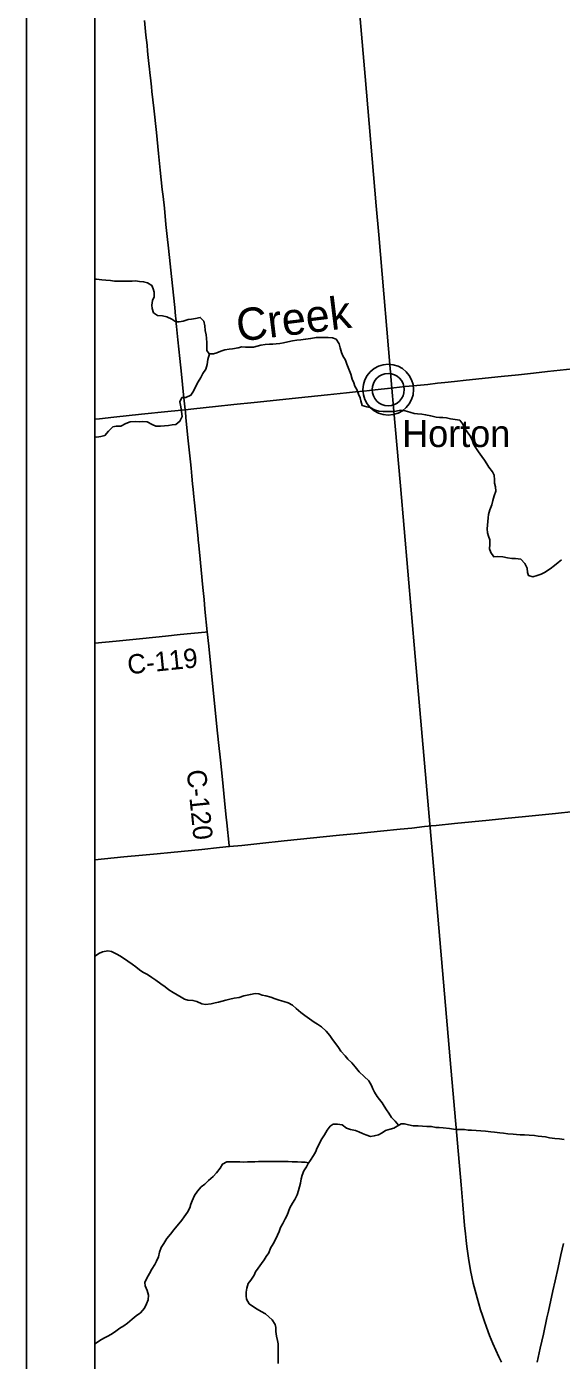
# Model space of a CAD drawing. Extents: x 0 to 34, y 0 to 22.
# Drawn here: x 2 to 2.784, y 18.655 to 20.61 of the extents above; entities that cross this region are included whole.
import ezdxf

# ---------------------------------------------------------------- set-up
doc = ezdxf.new("R2010")
doc.units = 0
for name, color, linetype in [('GM_X_Corporation', 7, 'Continuous'), ('GM_X_County_Road', 7, 'Continuous'), ('GM_X_County_Road_Text', 7, 'Continuous'), ('GM_X_Minor_River', 7, 'Continuous'), ('GM_X_Minor_River_Text', 7, 'Continuous'), ('GM_X_Rail_Line', 7, 'Continuous'), ('GM_X_Unincorporated', 7, 'Continuous'), ('GM_X_Unincorporated_Location', 7, 'Continuous'), ('GM_X_Unincorporated_Text', 7, 'Continuous'), ('SH_Data', 7, 'Continuous')]:
    doc.layers.add(name, color=color, linetype=linetype)

msp = doc.modelspace()

# ---------------------------------------------------------------- linework, layer by layer
at = {"layer": 'GM_X_Corporation'}
msp.add_lwpolyline([(2.8444, 15.5792), (2.8939, 16.1007), (2.9069, 16.2381), (2.9254, 16.4061), (2.988, 17.0603), (3.0331, 17.5172), (3.0637, 17.8164), (3.0931, 18.1263), (3.1112, 18.3014), (3.1559, 18.7686), (3.1859, 19.0395), (3.2287, 19.5029), (3.2417, 19.6403), (3.2592, 19.8236), (3.2953, 20.1573), (3.3575, 20.7908), (3.3687, 20.9), (2.1, 20.9), (2.1, 14.1)], dxfattribs=at)
msp.add_lwpolyline([(3.3687, 20.9), (2.1, 20.9), (2.1, 18.2085), (2.1311, 18.2055), (2.4093, 18.1831), (2.8083, 18.1509), (3.0252, 18.1335), (3.0931, 18.1263), (3.1112, 18.3014), (3.1559, 18.7686), (3.1859, 19.0395), (3.2287, 19.5029), (3.2417, 19.6403), (3.2592, 19.8236), (3.2953, 20.1573), (3.3575, 20.7908)], close=True, dxfattribs=at)
at = {"layer": 'GM_X_County_Road'}
for points in [[(2.2649, 19.7224), (2.2615, 19.7559), (2.2601, 19.7698), (2.2584, 19.7875), (2.2533, 19.8391), (2.2519, 19.8533), (2.2515, 19.8571), (2.2513, 19.8592), (2.246, 19.9118), (2.2447, 19.9255), (2.2441, 19.9316), (2.2433, 19.9388), (2.2427, 19.9452), (2.2422, 19.9507), (2.2416, 19.9566), (2.241, 19.9625), (2.2402, 19.9715), (2.2365, 20.0067), (2.235, 20.0222), (2.2336, 20.0364), (2.2327, 20.0456), (2.2324, 20.048), (2.2319, 20.0524), (2.2302, 20.0698), (2.2271, 20.1004), (2.2247, 20.1232), (2.2219, 20.1507), (2.2199, 20.1699), (2.2194, 20.1747), (2.2191, 20.1781), (2.2187, 20.1823), (2.2183, 20.1854), (2.2171, 20.198), (2.2137, 20.2299), (2.2078, 20.2849), (2.2061, 20.3021), (2.2043, 20.3195), (2.2019, 20.3433), (2.2, 20.3606), (2.1989, 20.3708), (2.1959, 20.3992), (2.1933, 20.4236), (2.1902, 20.4545), (2.1864, 20.4903), (2.1837, 20.5147), (2.183, 20.5212), (2.182, 20.5302), (2.1807, 20.5422), (2.1802, 20.5472), (2.1793, 20.5555), (2.1784, 20.5644), (2.1774, 20.5737), (2.1765, 20.5823), (2.1749, 20.5969), (2.1726, 20.6185)], [(2.1, 20.0341), (2.107, 20.0349), (2.128, 20.0372), (2.1682, 20.0414), (2.2071, 20.0453), (2.2222, 20.047), (2.2324, 20.048), (2.2451, 20.0493), (2.2769, 20.0527), (2.3038, 20.0557), (2.3338, 20.0589), (2.3662, 20.0622), (2.3987, 20.0656), (2.4413, 20.07), (2.4691, 20.073), (2.4821, 20.0742), (2.4945, 20.0755), (2.5112, 20.0773), (2.5337, 20.0797), (2.5386, 20.0802), (2.555, 20.082), (2.5668, 20.0831), (2.5881, 20.0853), (2.6023, 20.0869), (2.6131, 20.0881), (2.6273, 20.0897), (2.6446, 20.0915), (2.6956, 20.0968), (2.7213, 20.0993), (2.7432, 20.1017), (2.7639, 20.1039), (2.801, 20.1078)], [(2.1, 19.7059), (2.1312, 19.7089), (2.1705, 19.713), (2.2035, 19.7163), (2.2252, 19.7184), (2.2616, 19.7221), (2.2649, 19.7224)], [(2.2973, 19.4077), (2.2971, 19.4094), (2.2935, 19.4428), (2.2926, 19.4508), (2.291, 19.465), (2.287, 19.5059), (2.2842, 19.5343), (2.2815, 19.5603), (2.279, 19.5834), (2.2749, 19.623), (2.2725, 19.6468), (2.2704, 19.6669), (2.267, 19.7015), (2.2649, 19.7224)], [(2.1, 19.3883), (2.1426, 19.3926), (2.1701, 19.3952), (2.1914, 19.3972), (2.2115, 19.3993), (2.2567, 19.4037), (2.2826, 19.4063), (2.2969, 19.4077), (2.2973, 19.4077), (2.3157, 19.4096), (2.3417, 19.4123), (2.3778, 19.416), (2.4588, 19.4243), (2.4857, 19.4271), (2.5188, 19.4304), (2.5479, 19.4333), (2.5649, 19.435), (2.5834, 19.437), (2.589, 19.4377), (2.593, 19.438), (2.6007, 19.4389), (2.6276, 19.4416), (2.678, 19.4466), (2.7012, 19.4489), (2.7315, 19.4519), (2.7757, 19.4564), (2.8023, 19.4592)], [(2.7488, 18.6522), (2.7532, 18.6726), (2.7577, 18.6932), (2.763, 18.717), (2.7652, 18.7268), (2.7716, 18.7564), (2.7748, 18.7712), (2.7792, 18.7909), (2.7833, 18.8094), (2.7871, 18.8261)]]:
    msp.add_lwpolyline(points, dxfattribs=at)
at = {"layer": 'GM_X_Minor_River'}
for points in [[(2.4635, 20.1273), (2.4615, 20.1321), (2.4599, 20.1386), (2.4584, 20.1449), (2.4538, 20.1516), (2.4487, 20.1535), (2.4423, 20.1538), (2.4372, 20.1539), (2.4304, 20.154), (2.4247, 20.1539), (2.4165, 20.1527), (2.4091, 20.1513), (2.4023, 20.1506), (2.3964, 20.1501), (2.39, 20.1491), (2.3828, 20.1476), (2.3765, 20.1462), (2.3712, 20.1453), (2.3661, 20.1445), (2.3611, 20.1442), (2.356, 20.144), (2.35, 20.1436), (2.3435, 20.1425), (2.3382, 20.1411), (2.3325, 20.14), (2.3278, 20.1397), (2.3209, 20.14), (2.3156, 20.1401), (2.3103, 20.139), (2.3018, 20.1372), (2.297, 20.1369), (2.2908, 20.136), (2.2849, 20.1337), (2.2788, 20.1317), (2.2739, 20.13), (2.2676, 20.1299), (2.2641, 20.1347), (2.2641, 20.1395), (2.2642, 20.1461), (2.2636, 20.1528), (2.2631, 20.1577), (2.262, 20.1642), (2.2615, 20.171), (2.2599, 20.1777), (2.2545, 20.1833), (2.2477, 20.182), (2.2416, 20.1806), (2.2369, 20.1801), (2.2296, 20.1781), (2.2236, 20.1771), (2.2186, 20.1769), (2.213, 20.1806), (2.2055, 20.1843), (2.1991, 20.1856), (2.1919, 20.1864), (2.1861, 20.1903), (2.1841, 20.1964), (2.1836, 20.2012), (2.1846, 20.208), (2.187, 20.2138), (2.1869, 20.2205), (2.1854, 20.2254), (2.1838, 20.2302), (2.177, 20.2339), (2.1714, 20.2357), (2.1653, 20.2362), (2.1596, 20.237), (2.1545, 20.2367), (2.149, 20.2366), (2.1441, 20.2367), (2.1367, 20.2366), (2.1288, 20.2367), (2.1229, 20.2373), (2.1159, 20.238), (2.1104, 20.2387), (2.1025, 20.2393), (2.1, 20.2394)], [(2.2679, 20.1299), (2.2658, 20.1218), (2.2647, 20.1144), (2.2628, 20.1076), (2.2585, 20.1014), (2.2556, 20.0955), (2.2517, 20.089), (2.2482, 20.0827), (2.2445, 20.0752), (2.2409, 20.0692), (2.2334, 20.0662), (2.2276, 20.0658), (2.2248, 20.0595), (2.2262, 20.0523), (2.2273, 20.0456), (2.2278, 20.0384), (2.2248, 20.0311), (2.2189, 20.0264), (2.2136, 20.0259), (2.2081, 20.0252), (2.202, 20.0247), (2.1965, 20.0241), (2.1893, 20.024), (2.184, 20.0265), (2.1767, 20.0304), (2.1703, 20.0309), (2.1652, 20.0304), (2.1589, 20.0309), (2.1519, 20.0302), (2.1454, 20.0278), (2.1382, 20.0241), (2.1314, 20.0238), (2.1266, 20.0228), (2.1201, 20.0166), (2.1147, 20.0104), (2.1086, 20.0088), (2.103, 20.0081), (2.1, 20.0086)], [(2.7843, 19.8279), (2.7795, 19.8242), (2.7742, 19.8197), (2.7677, 19.8147), (2.7593, 19.8095), (2.7543, 19.8071), (2.7486, 19.8051), (2.7423, 19.8032), (2.7361, 19.8049), (2.7343, 19.8096), (2.7338, 19.8161), (2.7303, 19.8228), (2.7245, 19.8291), (2.7169, 19.8302), (2.7115, 19.8301), (2.7052, 19.8309), (2.6981, 19.8327), (2.691, 19.8328), (2.685, 19.8325), (2.6809, 19.8389), (2.6789, 19.844), (2.679, 19.8507), (2.6793, 19.8573), (2.6774, 19.8627), (2.6758, 19.8678), (2.6753, 19.8737), (2.6756, 19.879), (2.6764, 19.8845), (2.6767, 19.8898), (2.6773, 19.8946), (2.6793, 19.9016), (2.682, 19.9085), (2.6834, 19.915), (2.6854, 19.922), (2.6878, 19.9286), (2.6873, 19.9349), (2.6862, 19.9404), (2.6863, 19.9453), (2.6858, 19.952), (2.6829, 19.9571), (2.6779, 19.9637), (2.6747, 19.969), (2.6714, 19.9744), (2.6673, 19.9796), (2.6624, 19.9863), (2.6587, 19.992), (2.6554, 19.9976), (2.6536, 20.0026), (2.6505, 20.0096), (2.6469, 20.0144), (2.6427, 20.0204), (2.6395, 20.0267), (2.6351, 20.033), (2.6286, 20.0337), (2.6215, 20.0349), (2.6158, 20.0361), (2.6101, 20.0368), (2.6052, 20.0368), (2.6003, 20.0373), (2.5926, 20.0389), (2.585, 20.0407), (2.5793, 20.0418), (2.5733, 20.0419), (2.5684, 20.0427), (2.5621, 20.0443), (2.555, 20.0467), (2.548, 20.0473), (2.5421, 20.0461), (2.5368, 20.0456), (2.5305, 20.0453), (2.5228, 20.0454), (2.5164, 20.0461), (2.5099, 20.0481), (2.5037, 20.0514), (2.4988, 20.0522), (2.4922, 20.0542), (2.4902, 20.0609), (2.4892, 20.0656), (2.4866, 20.0708), (2.4842, 20.0775), (2.4813, 20.0827), (2.4796, 20.0874), (2.4774, 20.0928), (2.4756, 20.1), (2.4736, 20.105), (2.4716, 20.1101), (2.4696, 20.1151), (2.4674, 20.1206), (2.4635, 20.1273)], [(2.5455, 18.9994), (2.5402, 19.0052), (2.535, 19.0106), (2.5309, 19.0171), (2.5279, 19.0219), (2.5244, 19.0273), (2.5211, 19.0321), (2.5175, 19.0369), (2.5142, 19.0417), (2.5101, 19.048), (2.5077, 19.0528), (2.5055, 19.0578), (2.5018, 19.0645), (2.4949, 19.0708), (2.4878, 19.0774), (2.4818, 19.085), (2.477, 19.0906), (2.4708, 19.0964), (2.4669, 19.1012), (2.4608, 19.1081), (2.4574, 19.1135), (2.4533, 19.1185), (2.4485, 19.1248), (2.4446, 19.1308), (2.4392, 19.1373), (2.4325, 19.1435), (2.4267, 19.1473), (2.4218, 19.1506), (2.415, 19.1551), (2.4079, 19.1603), (2.4019, 19.1646), (2.3952, 19.1702), (2.3899, 19.1752), (2.3835, 19.1787), (2.3769, 19.1809), (2.3701, 19.1825), (2.3645, 19.1847), (2.3579, 19.1871), (2.3509, 19.1889), (2.3454, 19.1901), (2.3406, 19.1921), (2.3353, 19.1923), (2.3282, 19.1911), (2.3233, 19.1898), (2.3186, 19.1889), (2.3115, 19.1868), (2.3043, 19.1855), (2.2979, 19.1841), (2.292, 19.1829), (2.2868, 19.1814), (2.2815, 19.1798), (2.2766, 19.1787), (2.2705, 19.1773), (2.2623, 19.1763), (2.2569, 19.1775), (2.2497, 19.1806), (2.2439, 19.1824), (2.2365, 19.1829), (2.2316, 19.1843), (2.2265, 19.1872), (2.2209, 19.1905), (2.2149, 19.194), (2.2087, 19.1977), (2.2029, 19.202), (2.1967, 19.2064), (2.1894, 19.2119), (2.1836, 19.2161), (2.177, 19.2204), (2.1704, 19.2239), (2.1655, 19.227), (2.1601, 19.2313), (2.1545, 19.2355), (2.1483, 19.2396), (2.1376, 19.247), (2.1312, 19.2507), (2.1246, 19.254), (2.119, 19.2548), (2.1112, 19.2536), (2.106, 19.2512), (2.1009, 19.2477), (2.1, 19.2471)], [(2.7239, 18.9855), (2.7185, 18.986), (2.7134, 18.9863), (2.7056, 18.9869), (2.6994, 18.9876), (2.6939, 18.9882), (2.6859, 18.9893), (2.6808, 18.9899), (2.6729, 18.9906), (2.6659, 18.9911), (2.6591, 18.9914), (2.6525, 18.9919), (2.6476, 18.9923), (2.6423, 18.993), (2.6364, 18.9932), (2.6309, 18.9933), (2.626, 18.9938), (2.6203, 18.9944), (2.6107, 18.9955), (2.605, 18.996), (2.6001, 18.9962), (2.5935, 18.9973), (2.5869, 18.9976), (2.5806, 18.9982), (2.5742, 18.9983), (2.567, 18.9986), (2.56, 18.9998), (2.5542, 19.0012), (2.549, 19.0013), (2.5431, 18.9982), (2.5382, 18.995), (2.5329, 18.9938), (2.526, 18.9916), (2.5212, 18.988), (2.5161, 18.9853), (2.5096, 18.9837), (2.5041, 18.983), (2.4973, 18.9854), (2.4924, 18.9873), (2.4872, 18.9895), (2.4823, 18.9916), (2.4751, 18.9933), (2.4689, 18.9949), (2.4629, 18.9997), (2.4557, 19.0009), (2.4497, 19.001), (2.4449, 18.9979), (2.4406, 18.992), (2.4368, 18.9851), (2.4321, 18.9779), (2.4294, 18.9726), (2.4259, 18.9662), (2.4237, 18.96), (2.4208, 18.9551), (2.4162, 18.948), (2.4129, 18.9431), (2.4102, 18.9382), (2.4065, 18.9325), (2.4038, 18.9261), (2.4026, 18.9208), (2.4017, 18.9146), (2.4003, 18.9089), (2.3987, 18.9038), (2.3968, 18.8974), (2.3933, 18.8906), (2.3898, 18.8849), (2.3857, 18.8785), (2.3822, 18.8676), (2.3791, 18.8621), (2.3757, 18.8555), (2.3724, 18.8493), (2.3701, 18.8438), (2.3676, 18.8382), (2.3654, 18.8327), (2.3615, 18.8257), (2.3578, 18.8191), (2.3551, 18.8125), (2.351, 18.8071), (2.3483, 18.8022), (2.3443, 18.7966), (2.3396, 18.7898), (2.3356, 18.7845), (2.3338, 18.7796), (2.3288, 18.7723), (2.3249, 18.7674), (2.323, 18.7606), (2.3219, 18.7545), (2.322, 18.7492), (2.3225, 18.7443), (2.3261, 18.7378), (2.3311, 18.7341), (2.3381, 18.7296), (2.3437, 18.7265), (2.3501, 18.7228), (2.3602, 18.7143), (2.3646, 18.7074), (2.3653, 18.7027), (2.3654, 18.6968), (2.3665, 18.6903), (2.3679, 18.6838), (2.3686, 18.6789)], [(2.788, 18.9785), (2.7812, 18.9792), (2.7746, 18.9797), (2.7667, 18.9809), (2.761, 18.9822), (2.7553, 18.983), (2.75, 18.9834), (2.7448, 18.9841), (2.7368, 18.9848), (2.73, 18.9853), (2.7239, 18.9855)], [(2.4138, 18.9444), (2.408, 18.9454), (2.4031, 18.9453), (2.3974, 18.9456), (2.3893, 18.9457), (2.3836, 18.946), (2.376, 18.9461), (2.3707, 18.946), (2.3645, 18.9464), (2.3592, 18.9463), (2.3535, 18.946), (2.3473, 18.9463), (2.3401, 18.9462), (2.3346, 18.9459), (2.3287, 18.9458), (2.3238, 18.9455), (2.3181, 18.9454), (2.3126, 18.9455), (2.3071, 18.9457), (2.2933, 18.9459), (2.2874, 18.9424), (2.2837, 18.9364), (2.2783, 18.9296), (2.2737, 18.9244), (2.2668, 18.9182), (2.2614, 18.9131), (2.2561, 18.9089), (2.2505, 18.9025), (2.2459, 18.8963), (2.2425, 18.8885), (2.2408, 18.8836), (2.2394, 18.8781), (2.2359, 18.8717), (2.2311, 18.8652), (2.2276, 18.8601), (2.216, 18.8462), (2.211, 18.8398), (2.2058, 18.8332), (2.201, 18.8261), (2.1973, 18.8203), (2.195, 18.8133), (2.1932, 18.8063), (2.1902, 18.8003), (2.1879, 18.7953), (2.1834, 18.7886), (2.1803, 18.782), (2.1761, 18.7754), (2.1735, 18.7688), (2.1738, 18.764), (2.1768, 18.7572), (2.1786, 18.7503), (2.1781, 18.7433), (2.1759, 18.7374), (2.173, 18.731), (2.1667, 18.7243), (2.1607, 18.7202), (2.1548, 18.7149), (2.1477, 18.7092), (2.1424, 18.7054), (2.1366, 18.7017), (2.1309, 18.6976), (2.1257, 18.6939), (2.12, 18.6908), (2.1153, 18.6882), (2.1088, 18.6847), (2.1008, 18.6795), (2.1, 18.6788)], [(2.3686, 18.6789), (2.3689, 18.674), (2.3686, 18.6502)]]:
    msp.add_lwpolyline(points, dxfattribs=at)
at = {"layer": 'GM_X_Rail_Line'}
msp.add_lwpolyline([(2.6961, 18.6519), (2.6924, 18.6598), (2.688, 18.6697), (2.6836, 18.6796), (2.6789, 18.691), (2.6742, 18.7034), (2.6709, 18.7129), (2.6683, 18.7204), (2.6657, 18.7287), (2.663, 18.7375), (2.6604, 18.7465), (2.6577, 18.7571), (2.655, 18.7678), (2.651, 18.7863), (2.6479, 18.8047), (2.6454, 18.8215), (2.6443, 18.8305), (2.6433, 18.8402), (2.6422, 18.8525), (2.6397, 18.8826), (2.6372, 18.9118), (2.6212, 19.0951), (2.6029, 19.3056), (2.5928, 19.4241), (2.5699, 19.6866), (2.5482, 19.9365), (2.5381, 20.0512), (2.5357, 20.0799), (2.5162, 20.3044), (2.5126, 20.3469), (2.4962, 20.5367), (2.4826, 20.6948)], dxfattribs=at)
at = {"layer": 'GM_X_Unincorporated'}
for radius in [0.0372, 0.0236]:
    msp.add_circle((2.5302, 20.0775), radius, dxfattribs=at)
at = {"layer": 'GM_X_Unincorporated_Location'}
msp.add_line((2.5302, 20.0775), (2.5302, 20.0775), dxfattribs=at)
at = {"layer": 'SH_Data'}
for p, q in [((2, 21), (2, 14)), ((2.1, 20.9), (2.1, 14.1))]:
    msp.add_line(p, q, dxfattribs=at)

# ---------------------------------------------------------------- texts
at = {"layer": 'GM_X_County_Road_Text'}
for s, rotation, p in [('C-119', 5.7929, (2.1491, 19.6602)), ('C-120', 275.7928, (2.2346, 19.5193))]:
    msp.add_text(s, height=0.02841, rotation=rotation, dxfattribs=at).set_placement(p)
at = {"layer": 'GM_X_Minor_River_Text'}
msp.add_text('Creek', height=0.04735, rotation=7.0348, dxfattribs=at).set_placement((2.3104, 20.1478))
at = {"layer": 'GM_X_Unincorporated_Text'}
msp.add_text('Horton', height=0.03949, rotation=0, dxfattribs=at).set_placement((2.5507, 19.9934))

doc.saveas('drawing.dxf')
